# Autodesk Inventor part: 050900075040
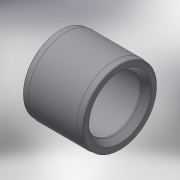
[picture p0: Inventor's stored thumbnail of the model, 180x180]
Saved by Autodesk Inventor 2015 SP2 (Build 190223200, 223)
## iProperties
Created: 2017-11
Part Number: 050900075040
Material: Generic
Description: PLASSON BUSHING-CEMENT PVC 75-40
Document SubType Name: Modeling
Designer: KIM
Density: 1 g/cm^3
Appearance: Default
Author: KIM
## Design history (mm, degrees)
derived "050900.ipt"
feature "Solid1::050900.ipt"
tag "TaggingFeature1"
body "Solid1"
other parameters: "d1" = 75, "d2" = 26, "d3" = 44, "d7" = 4.4, "d11" = 4.4, "d12" = 0.75, "d14" = 0.75, "d15" = 4.4, "d17" = 0.75, "d18" = 0.75, "d19" = 35.6, "d20" = 3.6, "d21" = 11.82, "D_" = 75, "L_" = 44, "l_" = 26, "z_" = 2
